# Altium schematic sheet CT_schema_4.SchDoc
size 322 x 229 mm
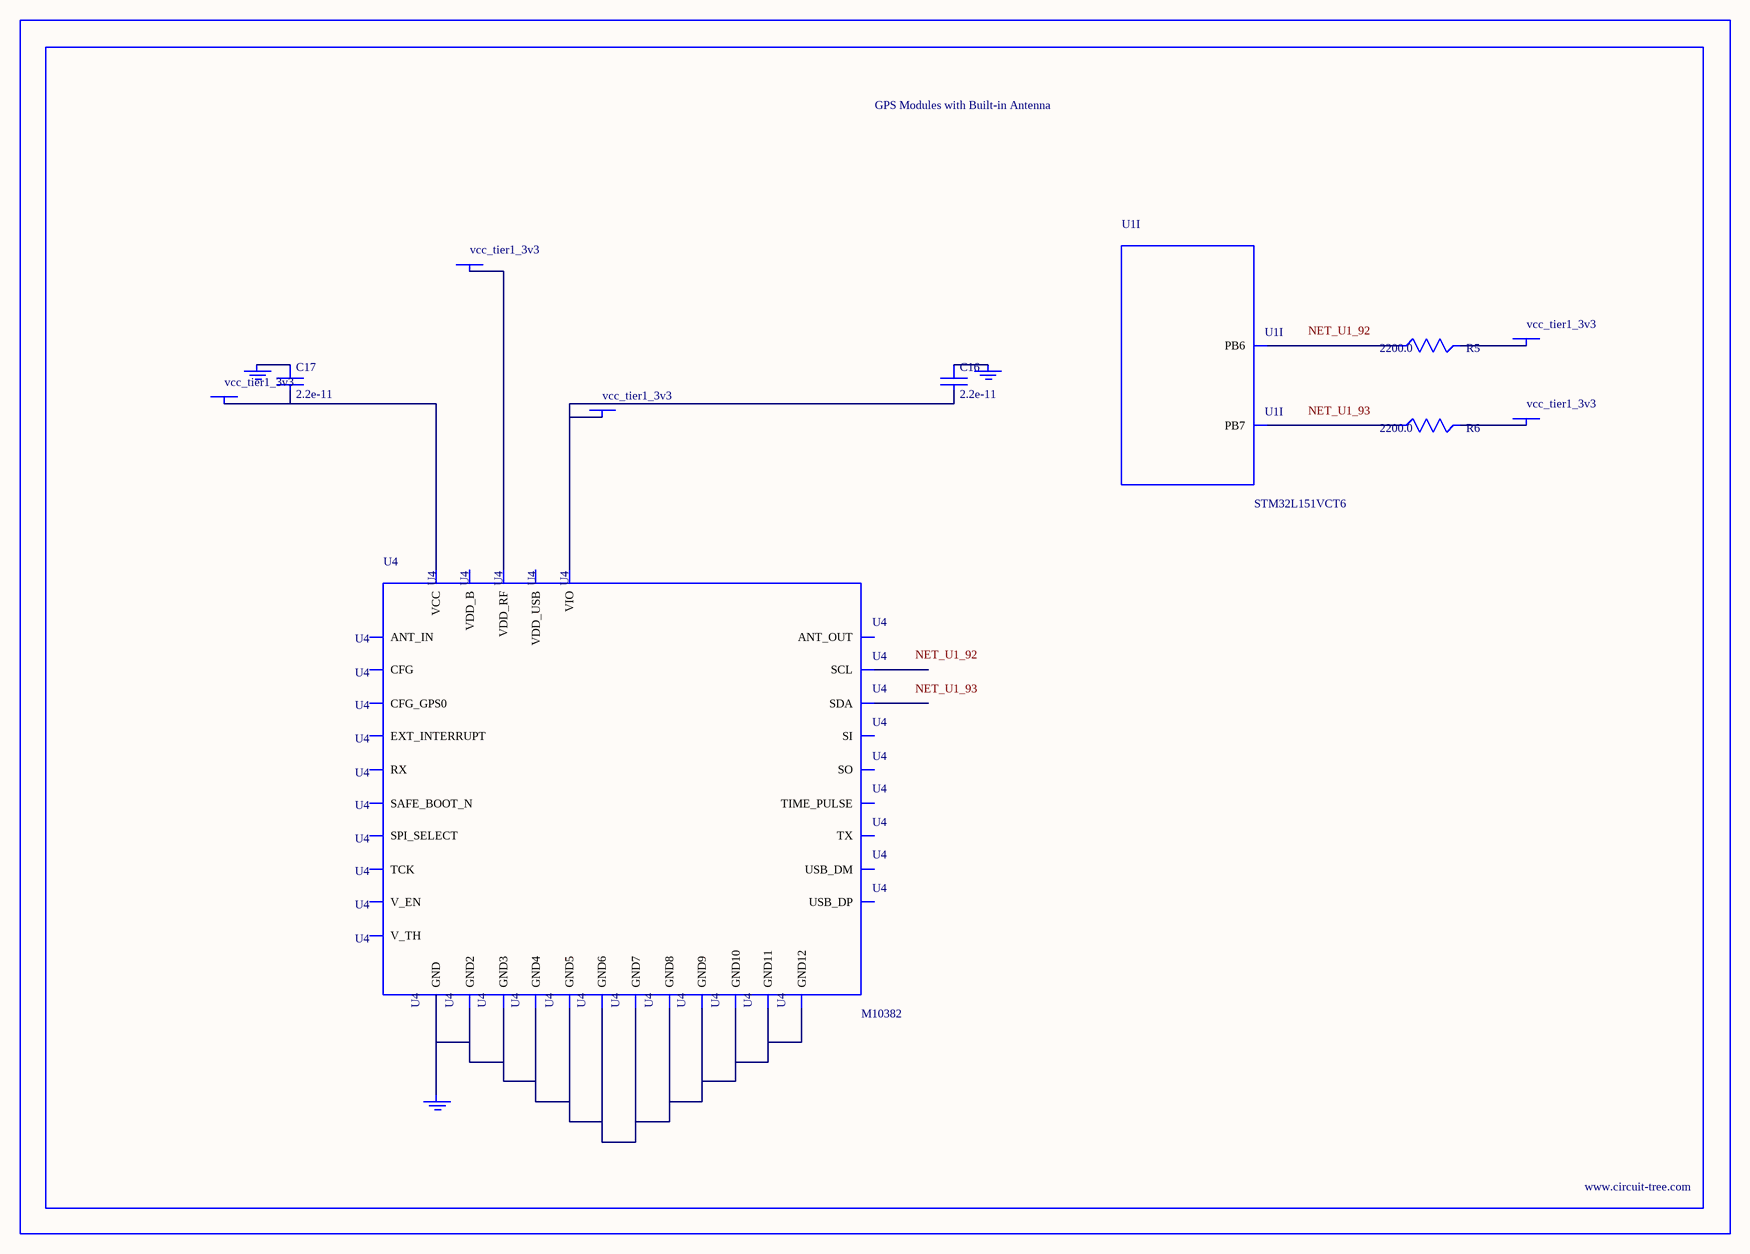
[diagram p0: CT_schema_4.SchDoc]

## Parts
BORDER3  (no value)
C16  2.2e-11  [C0402]
C17  2.2e-11  [C0402]
GND_INSTANCE_3_0  (no value)
GND_INSTANCE_3_1  (no value)
GND_INSTANCE_3_2  (no value)
POWER_INSTANCE_3_0  vcc_tier1_3v3
POWER_INSTANCE_3_1  vcc_tier1_3v3
POWER_INSTANCE_3_2  vcc_tier1_3v3
POWER_INSTANCE_3_3  vcc_tier1_3v3
POWER_INSTANCE_3_4  vcc_tier1_3v3
R5  2200.0  [R0603]
R6  2200.0  [R0603]
U1  STM32L151VCT6  [LQFP100]  (part I of 11)
U4  M10382  [M10382]

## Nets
NetC16_1: C16.1 GND_INSTANCE_3_0.0(GND)
NetC16_2: C16.2 POWER_INSTANCE_3_0.0(PWR) U4.5(VIO)
NetC17_1: C17.1 GND_INSTANCE_3_1.0(GND)
NetC17_2: C17.2 POWER_INSTANCE_3_2.0(PWR) U4.27(VCC)
NetGND_INSTANCE_3_2_0: GND_INSTANCE_3_2.0(GND) U4.2(GND) U4.4(GND2) U4.14(GND3) U4.17(GND4) U4.21(GND5) U4.24(GND6) U4.26(GND7) U4.28(GND8) U4.33(GND9) U4.34(GND10) U4.35(GND11) U4.36(GND12)
NetPOWER_INSTANCE_3_1_0: POWER_INSTANCE_3_1.0(PWR) U4.25(VDD_RF)
NetPOWER_INSTANCE_3_3_0: POWER_INSTANCE_3_3.0(PWR) R5.2
NetPOWER_INSTANCE_3_4_0: POWER_INSTANCE_3_4.0(PWR) R6.2
NetR5_1: R5.1 U1.92(PB6)
NetR6_1: R6.1 U1.93(PB7)

Not connected (* = marked no-connect by the designer): U4 1(ANT_IN) 3(ANT_OUT) 6(USB_DP) 7(USB_DM) 8(SO) 9(CFG_GPS0) 10(SPI_SELECT) 11(TX) 12(V_TH) 13(RX) 15(VDD_B) 16(SI) 18(SDA) 19(SCL) 20(SAFE_BOOT_N) 22(TCK) 23(TIME_PULSE) 29(EXT_INTERRUPT) 30(V_EN) 31(CFG) 32(VDD_USB)

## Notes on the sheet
- Labels drawn without touching a wire or pin: NET_U1_92, NET_U1_93

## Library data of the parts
BORDER3 = BORDER_PAGE3
C16 C17 = C0402C220K3RAC
GND_INSTANCE_3_0-GND_INSTANCE_3_2 = GND
POWER_INSTANCE_3_0-POWER_INSTANCE_3_4 = PWR
R5 R6 = RC0603JR-072K2L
